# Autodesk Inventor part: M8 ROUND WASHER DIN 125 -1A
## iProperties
Created: 2006-02
Part Number: M8 ROUND WASHER DIN 125 -1A
Material: Steel, Mild
Description: M8 ROUND WASHER FOR ANGLES
Document SubType Name: Modeling
Standard: DIN 125
Designer: Andy Moles
Standards Organization: DIN
Language: en-US
Size Designation: A 8.4
Categories: <MemberInstance><Categories><Category DisplayName="Fasteners" InternalName="e4da775c-781d-43d5-af7c-5136215cf5a6" Mnemonic="FSTN"><Category DisplayName="Washers
Mass: 1.83162 g
Surface Area: 4.13936 cm^2
Volume: 0.233031 cm^3
Density: 7.86 g/cm^3
Author: Andy Moles
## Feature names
1. Body [Extrusion]
